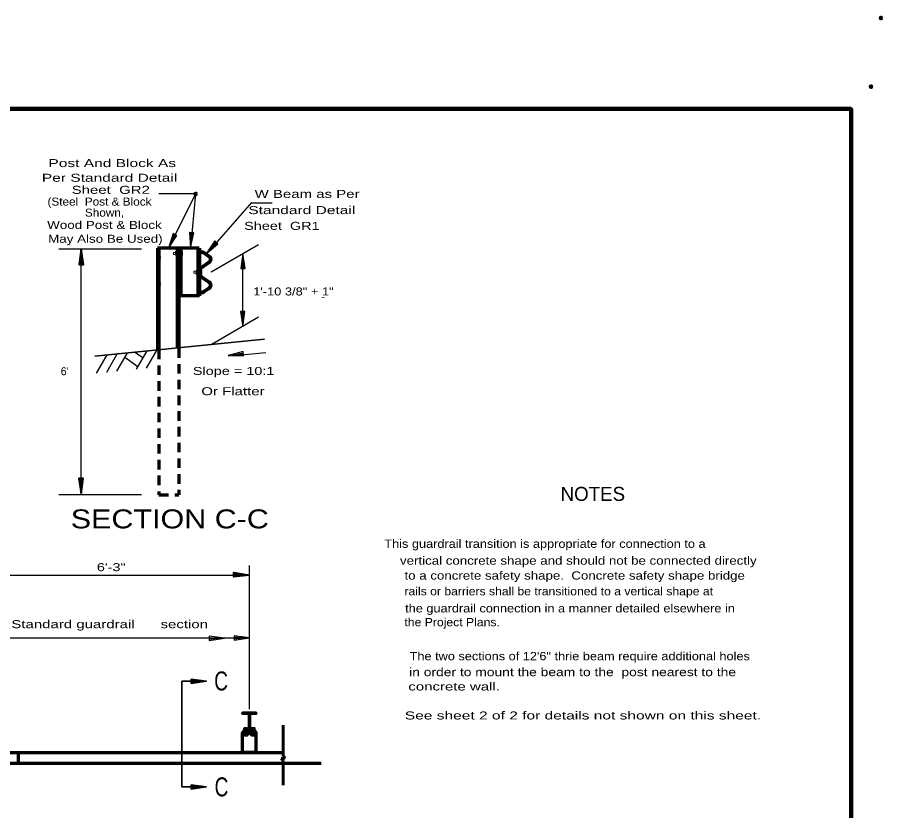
# Model space of a CAD drawing. Extents: x 856.9 to 891.7, y -2278.5 to -2254.7.
# Drawn here: x 877.8 to 891.69, y -2267.45 to -2254.69 of the extents above; entities that cross this region are included whole.
import ezdxf
from ezdxf.enums import TextEntityAlignment as Align

# ---------------------------------------------------------------- set-up
doc = ezdxf.new("R2010")
doc.units = 0
doc.header["$LTSCALE"] = 0.051
doc.header["$PDMODE"] = 32
doc.header["$PDSIZE"] = 0.0255
doc.linetypes.add('LONG_DASHED', pattern=[7.5, 6, -1.5])
doc.linetypes.add('MEDIUM_DASHED', pattern=[4.5, 3, -1.5])
doc.layers.add('1', color=7, linetype='Continuous', lineweight=70)
doc.layers.add('3', color=7, linetype='Continuous', lineweight=40)

msp = doc.modelspace()

# ---------------------------------------------------------------- linework, layer by layer
at = {"layer": '1', "lineweight": 25}
for p, q in [((880.66892, -2257.53383), (880.07492, -2257.53383)), ((880.66892, -2257.53383), (880.23017, -2258.40508)), ((880.66892, -2257.53383), (880.587, -2258.3985)), ((881.56692, -2257.669), (880.96692, -2258.35592)), ((881.89858, -2257.67933), (881.57108, -2257.67933)), ((880.91575, -2258.78625), (881.68142, -2258.34417)), ((879.79775, -2258.42267), (878.47283, -2258.42267)), ((878.82917, -2262.35175), (878.82917, -2258.42208)), ((881.42667, -2259.66767), (881.42667, -2258.4895)), ((880.91575, -2259.95133), (881.68142, -2259.50925)), ((879.71792, -2260.35017), (879.8875, -2260.05683)), ((879.881, -2260.33383), (880.04983, -2260.0405)), ((879.07792, -2260.41442), (879.24192, -2260.13075)), ((879.2405, -2260.398), (879.40425, -2260.1145)), ((879.40358, -2260.38167), (879.56733, -2260.09808)), ((879.73942, -2260.31292), (879.52858, -2260.16483)), ((879.82142, -2260.17008), (879.68775, -2260.077)), ((881.34483, -2260.12667), (881.79675, -2260.08133)), ((879.79775, -2262.37275), (878.47283, -2262.37275)), ((881.52925, -2263.50467), (881.52925, -2265.81658)), ((877.422, -2263.66417), (881.52925, -2263.66417)), ((877.456, -2264.66783), (881.52925, -2264.66783))]:
    msp.add_line(p, q, dxfattribs=at)
at = {"layer": '1'}
for p, q in [((880.726, -2258.40508), (880.0585, -2258.40508)), ((880.0585, -2258.40508), (880.0585, -2260.03775)), ((880.0795, -2258.40508), (880.0795, -2260.03775)), ((880.3735, -2258.40508), (880.3735, -2260.01483)), ((880.40108, -2258.40508), (880.40108, -2260.01483)), ((880.42908, -2258.40508), (880.42908, -2259.16933)), ((880.70233, -2258.40508), (880.70233, -2259.16933)), ((880.7285, -2258.40508), (880.7285, -2259.16933)), ((880.73192, -2258.45992), (880.737, -2258.45867)), ((880.74217, -2258.46592), (880.754, -2258.462)), ((880.75933, -2258.46867), (880.77167, -2258.46467)), ((880.77625, -2258.47183), (880.78808, -2258.46783)), ((880.79, -2258.47583), (880.798, -2258.47308)), ((880.79067, -2258.47642), (880.88767, -2258.54192)), ((880.891, -2258.53658), (880.79475, -2258.47125)), ((880.79942, -2258.48167), (880.8065, -2258.47892)), ((880.80583, -2258.48617), (880.809, -2258.481)), ((880.84708, -2258.51433), (880.85025, -2258.50908)), ((880.85025, -2258.51625), (880.8575, -2258.51433)), ((880.859, -2258.52225), (880.86608, -2258.52017)), ((880.86742, -2258.52817), (880.87458, -2258.52542)), ((880.87583, -2258.53408), (880.88308, -2258.53142)), ((880.88442, -2258.54), (880.89158, -2258.53733)), ((880.89283, -2258.54583), (880.89942, -2258.54392)), ((880.88767, -2258.62633), (880.7605, -2258.71408)), ((880.76383, -2258.71942), (880.89158, -2258.631)), ((880.80583, -2258.68275), (880.80975, -2258.68783)), ((880.84642, -2258.6545), (880.85025, -2258.65992)), ((880.84708, -2258.65517), (880.86475, -2258.65)), ((880.85625, -2258.648), (880.87517, -2258.642)), ((880.86808, -2258.64008), (880.88767, -2258.63358)), ((880.87967, -2258.63167), (880.89683, -2258.62633)), ((880.891, -2258.62392), (880.90342, -2258.61983)), ((880.89875, -2258.55242), (880.90458, -2258.55033)), ((880.90142, -2258.61208), (880.90992, -2258.60867)), ((880.90342, -2258.5595), (880.90908, -2258.55758)), ((880.90667, -2258.56667), (880.9125, -2258.5655)), ((880.90667, -2258.6015), (880.91375, -2258.59883)), ((880.90908, -2258.57458), (880.9145, -2258.57325)), ((880.90908, -2258.59225), (880.91575, -2258.58958)), ((880.90992, -2258.583), (880.91575, -2258.58125)), ((880.73567, -2258.76), (880.74217, -2258.758)), ((880.73567, -2258.76117), (880.73567, -2258.82292)), ((880.73567, -2258.76917), (880.74217, -2258.76717)), ((880.74217, -2258.77183), (880.73567, -2258.77183)), ((880.74217, -2258.81242), (880.73567, -2258.81242)), ((880.73567, -2258.82025), (880.74217, -2258.81833)), ((880.737, -2258.75142), (880.74358, -2258.74958)), ((880.73958, -2258.74167), (880.74675, -2258.73975)), ((880.74217, -2258.82292), (880.74217, -2258.76117)), ((880.74417, -2258.73183), (880.754, -2258.72858)), ((880.75333, -2258.72), (880.77117, -2258.71408)), ((880.76317, -2258.71283), (880.78208, -2258.70625)), ((880.77433, -2258.70492), (880.79475, -2258.69842)), ((880.78608, -2258.6965), (880.80517, -2258.69058)), ((880.798, -2258.6885), (880.80775, -2258.68542)), ((880.73633, -2258.82883), (880.74217, -2258.82675)), ((880.73758, -2258.83708), (880.74358, -2258.83533)), ((880.74033, -2258.84508), (880.74625, -2258.84308)), ((880.74417, -2258.85242), (880.75017, -2258.85017)), ((880.74867, -2258.85967), (880.75542, -2258.85692)), ((880.75542, -2258.86617), (880.7625, -2258.8635)), ((880.7605, -2258.87), (880.88767, -2258.95783)), ((880.76317, -2258.872), (880.77033, -2258.86925)), ((880.89158, -2258.95325), (880.76383, -2258.86483)), ((880.77167, -2258.878), (880.77883, -2258.87525)), ((880.78033, -2258.88375), (880.7875, -2258.88117)), ((880.78875, -2258.88975), (880.79592, -2258.88708)), ((880.79717, -2258.895), (880.80458, -2258.89292)), ((880.80583, -2258.9015), (880.80975, -2258.89617)), ((880.84642, -2258.92958), (880.85025, -2258.92442)), ((880.84758, -2258.93033), (880.85492, -2258.92833)), ((880.85625, -2258.93617), (880.86333, -2258.9335)), ((880.86475, -2258.94217), (880.872, -2258.9395)), ((880.87317, -2258.94792), (880.88042, -2258.94533)), ((880.88183, -2258.95392), (880.88892, -2258.95133)), ((880.89033, -2258.95967), (880.89683, -2258.95783)), ((880.88767, -2259.04225), (880.79067, -2259.10767)), ((880.79475, -2259.113), (880.891, -2259.0475)), ((880.8025, -2259.09992), (880.8065, -2259.0985)), ((880.80583, -2259.09792), (880.809, -2259.10258)), ((880.84708, -2259.06983), (880.85025, -2259.075)), ((880.84833, -2259.07233), (880.859, -2259.06917)), ((880.851, -2259.06717), (880.872, -2259.06058)), ((880.86333, -2259.05867), (880.88375, -2259.05217)), ((880.87517, -2259.05075), (880.89558, -2259.04425)), ((880.89558, -2259.035), (880.90592, -2259.03167)), ((880.89683, -2258.96633), (880.90342, -2258.96433)), ((880.902, -2258.97283), (880.90792, -2258.97083)), ((880.904, -2259.024), (880.91183, -2259.02133)), ((880.90592, -2258.98067), (880.91183, -2258.97875)), ((880.90792, -2259.01408), (880.9145, -2259.01217)), ((880.90858, -2258.98792), (880.9145, -2258.98658)), ((880.90992, -2258.99642), (880.91575, -2258.99442)), ((880.90992, -2259.005), (880.91575, -2259.003)), ((880.7285, -2259.16933), (880.40108, -2259.16933)), ((880.73192, -2259.123), (880.75075, -2259.11692)), ((880.73958, -2259.12483), (880.77883, -2259.11167)), ((880.76708, -2259.12025), (880.79942, -2259.10975)), ((880.79142, -2259.10767), (880.8085, -2259.10258)), ((881.423, -2266.50767), (881.423, -2266.19725)), ((881.64108, -2266.50767), (881.64108, -2266.19725)), ((882.07667, -2266.51742), (865.61517, -2266.51742)), ((882.68767, -2266.68917), (866.22875, -2266.68917))]:
    msp.add_line(p, q, dxfattribs=at)
at = {"layer": '1', "lineweight": 13}
msp.add_line((880.73108, -2258.79467), (880.73192, -2258.79542), dxfattribs=at)
at = {"layer": '1', "lineweight": 35}
msp.add_line((881.77775, -2259.8675), (879.05058, -2260.14058), dxfattribs=at)
at = {"layer": '1', "linetype": 'MEDIUM_DASHED'}
for p, q in [((880.0795, -2260.03775), (880.0795, -2262.37275)), ((880.40108, -2260.01483), (880.40108, -2262.37275)), ((880.0795, -2262.37275), (880.39975, -2262.37275))]:
    msp.add_line(p, q, dxfattribs=at)
at = {"layer": '1', "lineweight": 60}
for p, q in [((882.07608, -2266.07542), (882.07608, -2266.56858)), ((882.07608, -2266.56858), (882.1075, -2266.60583)), ((882.1075, -2266.60583), (882.044, -2266.60783)), ((882.044, -2266.60783), (882.07608, -2266.64317)), ((882.07608, -2266.64317), (882.07667, -2267.0415))]:
    msp.add_line(p, q, dxfattribs=at)
at = {"layer": '1', "linetype": 'LONG_DASHED'}
msp.add_line((877.81883, -2266.52475), (877.81883, -2266.70033), dxfattribs=at)
at = {"layer": '1', "lineweight": 25}
for points in [[(880.23017, -2258.40508), (880.36825, -2258.20067), (880.306, -2258.16925)], [(880.587, -2258.3985), (880.64142, -2258.15808), (880.57183, -2258.15158)], [(880.84058, -2258.495), (881.027, -2258.3335), (880.97508, -2258.287)], [(881.42667, -2258.4895), (881.39533, -2258.73375), (881.46533, -2258.73375)], [(881.42667, -2259.66767), (881.45808, -2259.4235), (881.38808, -2259.4235)], [(881.19175, -2260.13142), (881.43808, -2260.13858), (881.43158, -2260.06858)], [(881.13292, -2264.67633), (880.88867, -2264.645), (880.88867, -2264.71508)], [(881.53258, -2264.66783), (881.28833, -2264.6365), (881.28833, -2264.70658)]]:
    msp.add_lwpolyline(points, close=True, dxfattribs=at)
for points in [[(880.3525, -2258.19275), (880.25758, -2258.35075), (880.32108, -2258.17708)], [(880.34475, -2258.18875), (880.2995, -2258.26367), (880.32908, -2258.181)], [(880.62375, -2258.15608), (880.59292, -2258.33758), (880.58892, -2258.15292)], [(880.61517, -2258.1555), (880.60017, -2258.24183), (880.59808, -2258.15417)], [(881.01375, -2258.32167), (880.88133, -2258.44967), (880.9875, -2258.29842)], [(881.00733, -2258.31592), (880.94425, -2258.37658), (880.99417, -2258.30433)], [(881.41292, -2258.73375), (881.42667, -2258.55033), (881.44775, -2258.73375)], [(881.42133, -2258.73375), (881.42867, -2258.6465), (881.43917, -2258.73375)], [(881.44042, -2259.4235), (881.42667, -2259.60683), (881.40567, -2259.4235)], [(881.43192, -2259.4235), (881.42467, -2259.5105), (881.41417, -2259.4235)], [(881.43683, -2260.121), (881.25267, -2260.12558), (881.43275, -2260.08608)], [(881.4355, -2260.11233), (881.34833, -2260.11392), (881.43417, -2260.09483)], [(881.28833, -2264.65417), (881.47167, -2264.66783), (881.28833, -2264.68883)], [(880.88867, -2264.66267), (881.072, -2264.67633), (880.88867, -2264.69733)], [(880.88867, -2264.67117), (880.97558, -2264.67833), (880.88867, -2264.68883)], [(881.28833, -2264.66267), (881.3755, -2264.66983), (881.28833, -2264.68033)]]:
    msp.add_lwpolyline(points, dxfattribs=at)
at = {"layer": '1', "lineweight": 40}
for points in [[(878.82917, -2258.42208), (878.79767, -2258.66642), (878.86775, -2258.66642)], [(878.82917, -2262.35175), (878.86067, -2262.10742), (878.79042, -2262.10742)], [(881.527, -2263.66), (881.28283, -2263.69133), (881.28283, -2263.62125)]]:
    msp.add_lwpolyline(points, close=True, dxfattribs=at)
for points in [[(878.81542, -2258.66642), (878.82917, -2258.48292), (878.85, -2258.66642)], [(878.82392, -2258.66642), (878.83108, -2258.57925), (878.84167, -2258.66642)], [(878.84275, -2262.10742), (878.82917, -2262.29092), (878.80817, -2262.10742)], [(878.8345, -2262.10742), (878.82725, -2262.19458), (878.81658, -2262.10742)], [(881.28283, -2263.67367), (881.46625, -2263.66), (881.28283, -2263.639)], [(881.28283, -2263.66517), (881.36992, -2263.658), (881.28283, -2263.6475)]]:
    msp.add_lwpolyline(points, dxfattribs=at)
at = {"layer": '1', "lineweight": 13}
for points in [[(880.34742, -2258.47183), (880.31117, -2258.47183), (880.31117, -2258.50592), (880.34742, -2258.50592)], [(880.37283, -2258.45992), (880.34742, -2258.45992), (880.34742, -2258.51775), (880.37283, -2258.51775)], [(880.43308, -2258.462), (880.45867, -2258.462), (880.45867, -2258.52017), (880.43308, -2258.52017)], [(880.67675, -2258.775), (880.64058, -2258.775), (880.64058, -2258.80917), (880.67675, -2258.80917)], [(880.70233, -2258.76333), (880.67675, -2258.76333), (880.67675, -2258.82075), (880.70233, -2258.82075)], [(880.74217, -2258.76333), (880.76708, -2258.76333), (880.76708, -2258.82075), (880.74217, -2258.82075)]]:
    msp.add_lwpolyline(points, dxfattribs=at)
at = {"layer": '1'}
for points in [[(880.78408, -2258.46725), (880.7325, -2258.458), (880.73192, -2258.46392), (880.78283, -2258.47308)], [(880.78283, -2259.11108), (880.73192, -2259.12025), (880.7325, -2259.12608), (880.78408, -2259.11692)]]:
    msp.add_lwpolyline(points, dxfattribs=at)
at = {"layer": '1', "lineweight": 35}
for points in [[(880.44917, -2265.36417), (880.84208, -2265.36417), (880.59792, -2265.33267), (880.59792, -2265.40275), (880.84208, -2265.36417)], [(880.59792, -2265.35033), (880.78125, -2265.36417), (880.59792, -2265.38508)], [(880.59792, -2265.35033), (880.78125, -2265.36417), (880.59792, -2265.38508)], [(880.44917, -2265.36417), (880.44917, -2267.067), (880.84208, -2267.067)], [(880.59792, -2265.35883), (880.685, -2265.366), (880.59792, -2265.37658)], [(880.59792, -2265.35883), (880.685, -2265.366), (880.59792, -2265.37658)], [(880.59792, -2267.05325), (880.78125, -2267.067), (880.59792, -2267.088)], [(880.59792, -2267.05325), (880.78125, -2267.067), (880.59792, -2267.088)], [(880.59792, -2267.06175), (880.685, -2267.06892), (880.59792, -2267.07942)], [(880.59792, -2267.06175), (880.685, -2267.06892), (880.59792, -2267.07942)]]:
    msp.add_lwpolyline(points, dxfattribs=at)
for points in [[(880.84208, -2265.36417), (880.59792, -2265.33267), (880.59792, -2265.40275)], [(880.84208, -2267.067), (880.59792, -2267.03567), (880.59792, -2267.10567)], [(880.84208, -2267.067), (880.59792, -2267.03567), (880.59792, -2267.10567)]]:
    msp.add_lwpolyline(points, close=True, dxfattribs=at)
at = {"layer": '1', "lineweight": 60}
for points in [[(881.423, -2266.19725), (881.64108, -2266.19725), (881.64108, -2266.18658), (881.53717, -2266.18658), (881.53717, -2265.88675), (881.64108, -2265.88675), (881.64108, -2265.877), (881.423, -2265.877), (881.423, -2265.88675), (881.52725, -2265.88675), (881.52725, -2266.18658), (881.423, -2266.18658)], [(881.53717, -2266.20767), (881.64108, -2266.20767), (881.64108, -2266.19725), (881.423, -2266.19725), (881.423, -2266.20767)]]:
    msp.add_lwpolyline(points, close=True, dxfattribs=at)
for points in [[(881.44133, -2266.18658), (881.44133, -2266.16183), (881.49967, -2266.16183), (881.49967, -2266.18658)], [(881.45392, -2266.16183), (881.45392, -2266.12583), (881.48792, -2266.12583), (881.48792, -2266.16183)], [(881.62275, -2266.18658), (881.62275, -2266.16183), (881.56442, -2266.16183), (881.56442, -2266.18658)], [(881.61042, -2266.16183), (881.61042, -2266.12583), (881.57625, -2266.12583), (881.57625, -2266.16183)], [(881.44133, -2266.20767), (881.44133, -2266.23267), (881.49967, -2266.23267), (881.49967, -2266.20767)], [(881.62275, -2266.20767), (881.62275, -2266.23267), (881.56442, -2266.23267), (881.56442, -2266.20767)], [(881.53717, -2266.50767), (881.423, -2266.50767), (881.423, -2266.51742)], [(881.423, -2266.51742), (881.64108, -2266.51742), (881.64108, -2266.50767), (881.53717, -2266.50767)]]:
    msp.add_lwpolyline(points, dxfattribs=at)
at = {"layer": '1'}
for centre, radius, start, end in [((880.77943, -2258.49301), 0.02046, 55.803, 79.99905), ((880.77943, -2258.49301), 0.02652, 55.803, 79.99905), ((880.8587, -2258.58399), 0.05115, 304.74043, 55.80219), ((880.8587, -2258.58399), 0.0572, 304.74043, 55.80219), ((880.79315, -2258.7613), 0.0572, 124.73767, 180), ((880.79315, -2258.7613), 0.05115, 124.73767, 180), ((880.79315, -2258.82267), 0.0572, 180, 235.26233), ((880.79315, -2258.82267), 0.05115, 180, 235.26233), ((880.8587, -2258.99999), 0.05115, 304.19781, 55.25957), ((880.8587, -2258.99999), 0.0572, 304.19781, 55.25957), ((880.77943, -2259.09096), 0.02046, 280.00095, 304.197), ((880.77943, -2259.09096), 0.02652, 280.00095, 304.197)]:
    msp.add_arc(centre, radius, start, end, dxfattribs=at)
for p in [(891.67967, -2254.70517), (891.52133, -2255.80717), (880.66892, -2257.53383), (880.0795, -2258.56275), (880.0795, -2258.97942)]:
    msp.add_point(p, dxfattribs=at)
at = {"layer": '3', "lineweight": 158}
msp.add_line((891.2, -2256.16333), (858.7, -2256.16333), dxfattribs=at)
msp.add_lwpolyline([(891.2, -2256.16333), (891.2, -2277.16333), (858.7, -2277.16333)], dxfattribs=at)
at = {"layer": '3'}
msp.add_point((891.2, -2256.16333), dxfattribs=at)

# ---------------------------------------------------------------- texts
at = {"layer": '1'}
for s, height, width, p in [('Post And Block As ', 0.1286, 1.45, (878.30325, -2257.10133)), ('Per Standard Detail ', 0.1286, 1.45, (878.19758, -2257.337)), (' Sheet  GR2', 0.1286, 1.4, (878.60942, -2257.53117)), ('W Beam as Per ', 0.1286, 1.4, (881.61683, -2257.59717)), ('(Steel  Post & Block', 0.1286, 1.1, (878.28833, -2257.7205)), ('Shown,', 0.1286, 1.1, (878.88942, -2257.89742)), (' Standard Detail ', 0.1286, 1.45, (881.4455, -2257.85708)), ('Wood Post & Block', 0.1286, 1.25, (878.28383, -2258.09558)), ('  Sheet  GR1', 0.1286, 1.35, (881.31883, -2258.1105)), ('May Also Be Used)', 0.1286, 1.25, (878.29883, -2258.31808)), ('1\'-10 3/8" + 1"', 0.1286, 1.2, (881.59358, -2259.16542)), ('-', 0.1287, 1.1, (882.688, -2259.24442)), ('Slope = 10:1', 0.1286, 1.35, (880.62442, -2260.443)), ('Or Flatter', 0.1286, 1.4, (880.76, -2260.76942)), ('     This guardrail transition is appropriate for connection to a', 0.133, 1.15, (883.41667, -2263.22317)), (' vertical concrete shape and should not be connected directly ', 0.133, 1.2, (883.893, -2263.49425)), ('6\'-3"', 0.1286, 1.35, (879.08158, -2263.59825)), ('to a concrete safety shape.  Concrete safety shape bridge ', 0.133, 1.2, (884.02475, -2263.73425)), ('rails or barriers shall be transitioned to a vertical shape at ', 0.133, 1.1, (884.02383, -2263.98633)), ('the guardrail connection in a manner detailed elsewhere in ', 0.133, 1.15, (884.03517, -2264.26158)), ('the Project Plans.', 0.133, 1.1, (884.02383, -2264.48383)), ('Standard guardrail', 0.1286, 1.4, (877.70725, -2264.51483)), ('section', 0.1286, 1.4, (880.10467, -2264.51525)), ('The two sections of 12\'6" thrie beam require additional holes', 0.133, 1.15, (884.10692, -2265.0305)), ('C', 0.3059, 0.75, (880.96708, -2265.51683)), ('in order to mount the beam to the  post nearest to the ', 0.133, 1.25, (884.09942, -2265.28675)), ('concrete wall.', 0.1286, 1.4, (884.08617, -2265.51683)), ('See sheet 2 of 2 for details not shown on this sheet.', 0.1286, 1.45, (884.02975, -2265.98283)), ('C', 0.3059, 0.75, (880.97308, -2267.21967))]:
    msp.add_text(s, height=height, dxfattribs=dict(at, width=width)).set_placement(p)
for s, height, p in [("6'", 0.1286, (878.50017, -2260.44775)), ('NOTES', 0.225, (886.53267, -2262.46792))]:
    msp.add_text(s, height=height, dxfattribs=at).set_placement(p)
at = {"layer": '1', "width": 1.2}
msp.add_text('SECTION C-C', height=0.3052, dxfattribs=at).set_placement((880.25358, -2262.91042), align=Align.CENTER)

doc.saveas('drawing.dxf')
